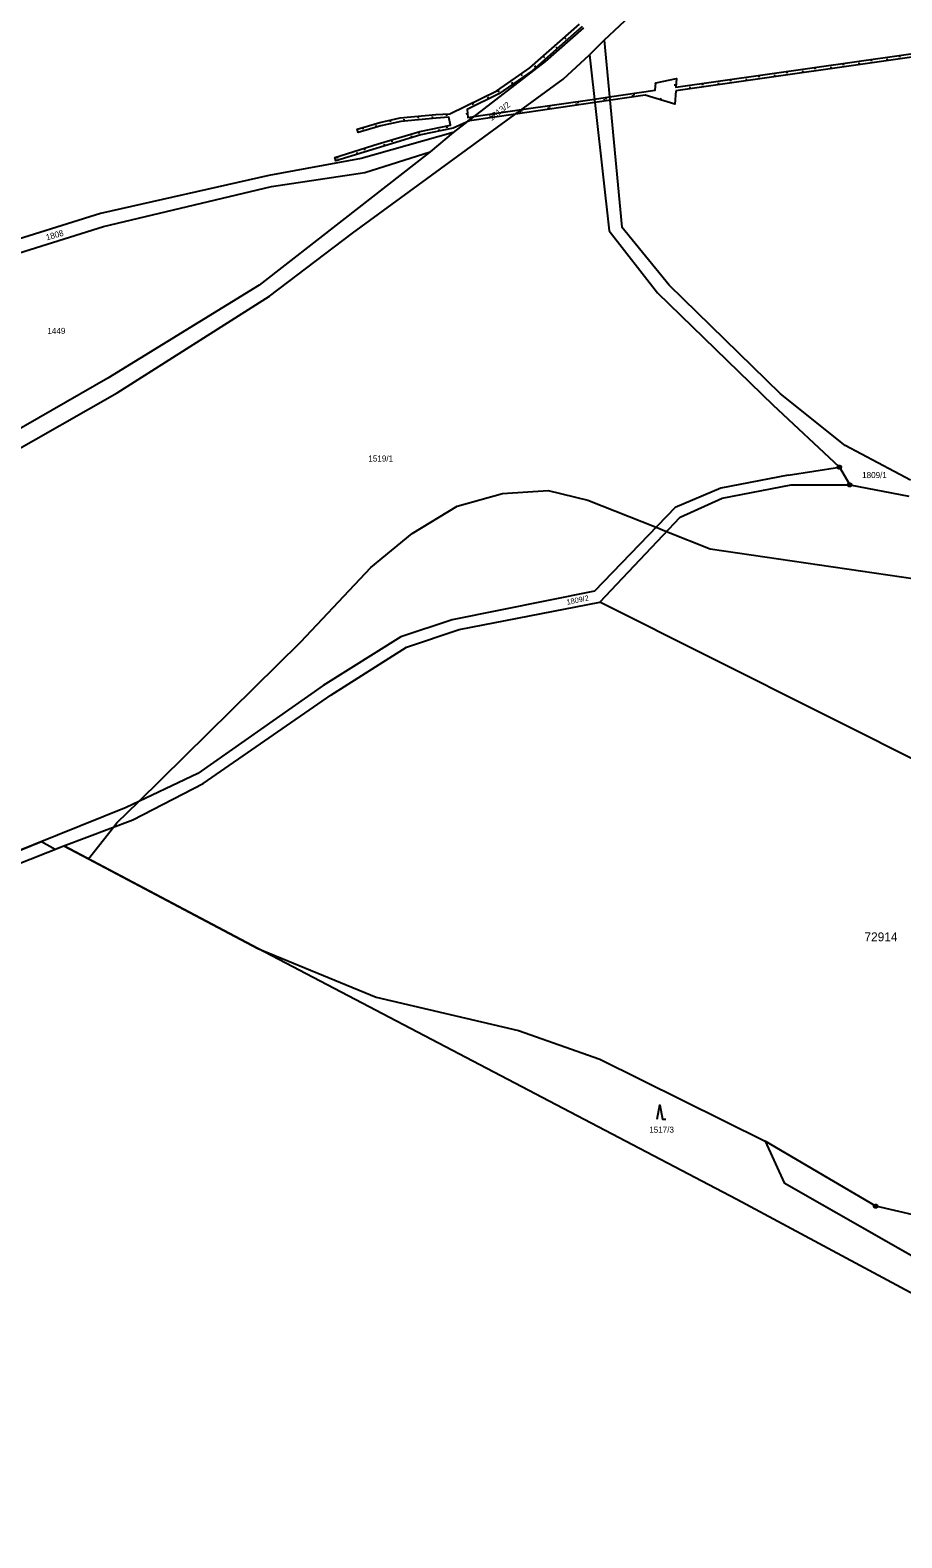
# Model space of a CAD drawing. Extents: x -779618 to -776429, y -1144546 to -1143350.
# Drawn here: x -778171.4 to -777926.1, y -1144528.8 to -1144104.5 of the extents above; entities that cross this region are included whole.
import ezdxf

# ---------------------------------------------------------------- set-up
doc = ezdxf.new("R2010")
doc.units = 0
for name, color, linetype in [('1', 7, 'Continuous'), ('11', 7, 'Continuous'), ('13', 7, 'Continuous'), ('2', 7, 'Continuous'), ('3', 7, 'Continuous'), ('8', 7, 'Continuous')]:
    doc.layers.add(name, color=color, linetype=linetype)

msp = doc.modelspace()

# ---------------------------------------------------------------- linework, layer by layer
at = {"layer": '1'}
for p, q in [((-778009.9, -1144107.25), (-777953.32, -1144054.13)), ((-778015.68, -1144103.79), (-778026.44, -1144113.3)), ((-778021.41, -1144118.27), (-778014.02, -1144111.36)), ((-778009.9, -1144107.25), (-778014.02, -1144111.36)), ((-778014.02, -1144111.36), (-778008.45, -1144160.92)), ((-778009.9, -1144107.25), (-778004.93, -1144159.92)), ((-778026.44, -1144113.3), (-778052.38, -1144133.24)), ((-778080.71, -1144161.6), (-778021.41, -1144118.27)), ((-778052.38, -1144133.24), (-778078.22, -1144140.59)), ((-778052.38, -1144133.24), (-778058.85, -1144138.68)), ((-778078.22, -1144140.59), (-778104.2, -1144145.33)), ((-778058.85, -1144138.68), (-778083.63, -1144158.04)), ((-778077.22, -1144144.48), (-778058.85, -1144138.68)), ((-778104.2, -1144145.33), (-778151.55, -1144156.01)), ((-778103.48, -1144148.43), (-778077.22, -1144144.48)), ((-778150.71, -1144159.71), (-778103.48, -1144148.43)), ((-778151.55, -1144156.01), (-778190.64, -1144168.24)), ((-778083.63, -1144158.04), (-778106.96, -1144176.23)), ((-778189.22, -1144171.73), (-778150.71, -1144159.71)), ((-778104.06, -1144179.35), (-778080.71, -1144161.6)), ((-778008.45, -1144160.92), (-777994.9, -1144178.38)), ((-777991.59, -1144176.2), (-778004.93, -1144159.92)), ((-778106.96, -1144176.23), (-778149.53, -1144202.42)), ((-777994.9, -1144178.38), (-777962.34, -1144209.95)), ((-777960.28, -1144206.84), (-777991.59, -1144176.2)), ((-778146.92, -1144206.52), (-778104.06, -1144179.35)), ((-778149.53, -1144202.42), (-778180.92, -1144220.4)), ((-778178.49, -1144224.58), (-778146.92, -1144206.52)), ((-777942.07, -1144221.33), (-777960.28, -1144206.84)), ((-777943.69, -1144227.42), (-777962.34, -1144209.95)), ((-777923.7, -1144231.09), (-777942.07, -1144221.33)), ((-777958.1, -1144229.69), (-777977.04, -1144233.33)), ((-777958.1, -1144229.69), (-777943.69, -1144227.42)), ((-777943.69, -1144227.42), (-777940.8, -1144232.44)), ((-777977.04, -1144233.33), (-777989.94, -1144238.83)), ((-777976.72, -1144236.21), (-777957.22, -1144232.42)), ((-777957.22, -1144232.42), (-777940.8, -1144232.44)), ((-777940.8, -1144232.44), (-777924.16, -1144235.57)), ((-777988.47, -1144241.5), (-777976.72, -1144236.21)), ((-777989.94, -1144238.83), (-778012.56, -1144262.31)), ((-778011.12, -1144265.48), (-777988.47, -1144241.5)), ((-778012.56, -1144262.31), (-778052.65, -1144270.41)), ((-778050.68, -1144273.14), (-778011.12, -1144265.48)), ((-777855.44, -1144343.58), (-778011.12, -1144265.48)), ((-778052.65, -1144270.41), (-778067.11, -1144275.18)), ((-778067.11, -1144275.18), (-778088.92, -1144288.94)), ((-778065.51, -1144278.13), (-778050.68, -1144273.14)), ((-778086.81, -1144291.59), (-778065.51, -1144278.13)), ((-778088.92, -1144288.94), (-778124.23, -1144313.7)), ((-778122.7, -1144316.51), (-778086.81, -1144291.59)), ((-778124.23, -1144313.7), (-778144.36, -1144323.21)), ((-778142.45, -1144326.7), (-778122.7, -1144316.51)), ((-778144.36, -1144323.21), (-778176.74, -1144336.28)), ((-778161.95, -1144334), (-778142.45, -1144326.7)), ((-778175.9, -1144339.55), (-778161.95, -1144334)), ((-778107.37, -1144362.89), (-778161.95, -1144334)), ((-778107.37, -1144362.89), (-778074.01, -1144376.57)), ((-777972.59, -1144433.55), (-778107.37, -1144362.89)), ((-778074.01, -1144376.57), (-778033.95, -1144386.03)), ((-778033.95, -1144386.03), (-778011.09, -1144394.05)), ((-778011.09, -1144394.05), (-777964.59, -1144417.15)), ((-777933.46, -1144435.4), (-777964.59, -1144417.15)), ((-777964.59, -1144417.15), (-777959.22, -1144428.87)), ((-777959.22, -1144428.87), (-777915.96, -1144453.57)), ((-777919.9, -1144461.76), (-777972.59, -1144433.55)), ((-777886.2, -1144446.52), (-777933.46, -1144435.4))]:
    msp.add_line(p, q, dxfattribs=at)
at = {"layer": '11'}
for points in [[(-778266.53, -1144276.65), (-778264.12, -1144275.43), (-778253.31, -1144268.82), (-778251.68, -1144267.86), (-778239.17, -1144258.55), (-778224.64, -1144251.87), (-778178.49, -1144224.58), (-778178.43, -1144228.31), (-778176.74, -1144336.28), (-778168.18, -1144332.82), (-778164.36, -1144334.96), (-778161.95, -1144334), (-778154.97, -1144337.7)], [(-778154.97, -1144337.7), (-778147.92, -1144328.75), (-778146.98, -1144327.55), (-778140.93, -1144321.59), (-778095.22, -1144276.56), (-778075.52, -1144255.69), (-778063.86, -1144246.1), (-778051.21, -1144238.41), (-778038.46, -1144234.87), (-778025.59, -1144234), (-778014.51, -1144236.71), (-777995.28, -1144244.37), (-777992.3, -1144245.55), (-777980.08, -1144250.42), (-777857.01, -1144268.43)], [(-778154.97, -1144337.7), (-778107.37, -1144362.89), (-778074.01, -1144376.57), (-778033.95, -1144386.03), (-778011.09, -1144394.05), (-777964.59, -1144417.15), (-777959.22, -1144428.87), (-777915.96, -1144453.57), (-777919.28, -1144460.47), (-777919.9, -1144461.76), (-777837.94, -1144505.62), (-777837.53, -1144505.84), (-777840.59, -1144507.92), (-777852.72, -1144518.48), (-777862.28, -1144528.78)]]:
    msp.add_lwpolyline(points, dxfattribs=at)
at = {"layer": '13'}
for p, q in [((-778021.04, -1144106.49), (-778020.71, -1144106.87)), ((-778023.1, -1144109.61), (-778023.43, -1144109.24)), ((-778029.09, -1144114.92), (-778029.42, -1144114.54)), ((-778027.04, -1144111.78), (-778026.71, -1144112.16)), ((-777950.63, -1144114.94), (-777950.56, -1144115.43)), ((-777945.98, -1144115.28), (-777946.05, -1144114.79)), ((-777942.71, -1144113.81), (-777942.64, -1144114.31)), ((-777938.06, -1144114.15), (-777938.13, -1144113.66)), ((-777934.79, -1144112.68), (-777934.72, -1144113.18)), ((-777930.14, -1144113.02), (-777930.21, -1144112.53)), ((-777926.87, -1144111.56), (-777926.8, -1144112.05)), ((-778035.55, -1144119.62), (-778035.84, -1144119.21)), ((-778033.25, -1144116.8), (-778032.96, -1144117.22)), ((-777995.55, -1144119.3), (-777995.45, -1144119.79)), ((-777982.31, -1144119.45), (-777982.24, -1144119.94)), ((-777977.66, -1144119.79), (-777977.73, -1144119.3)), ((-777974.39, -1144118.32), (-777974.32, -1144118.82)), ((-777969.74, -1144118.67), (-777969.81, -1144118.17)), ((-777966.47, -1144117.19), (-777966.4, -1144117.69)), ((-777961.82, -1144117.54), (-777961.89, -1144117.04)), ((-777958.55, -1144116.07), (-777958.48, -1144116.56)), ((-777953.9, -1144116.41), (-777953.97, -1144115.91)), ((-778042.35, -1144123.8), (-778042.57, -1144123.35)), ((-778039.82, -1144121.37), (-778039.53, -1144121.78)), ((-778009.68, -1144124.42), (-778009.75, -1144123.92)), ((-778009.48, -1144123.38), (-778009.41, -1144123.87)), ((-778001.76, -1144123.27), (-778001.83, -1144122.77)), ((-778001.57, -1144122.23), (-778001.49, -1144122.72)), ((-777994, -1144124.1), (-777993.85, -1144123.62)), ((-777989.66, -1144119.95), (-777990.15, -1144119.92)), ((-777985.58, -1144120.92), (-777985.65, -1144120.43)), ((-778054.28, -1144128.02), (-778054.26, -1144128.52)), ((-778048.31, -1144128.03), (-778048.81, -1144128.07)), ((-778046.99, -1144124.91), (-778046.77, -1144125.36)), ((-778041.15, -1144128), (-778041.08, -1144128.49)), ((-778033.43, -1144127.88), (-778033.5, -1144127.39)), ((-778033.23, -1144126.85), (-778033.16, -1144127.34)), ((-778025.51, -1144126.73), (-778025.58, -1144126.23)), ((-778025.31, -1144125.69), (-778025.24, -1144126.19)), ((-778017.6, -1144125.57), (-778017.67, -1144125.08)), ((-778017.4, -1144124.54), (-778017.33, -1144125.03)), ((-778077.89, -1144131.87), (-778077.75, -1144132.35)), ((-778073.9, -1144131.74), (-778074.04, -1144131.26)), ((-778070.16, -1144129.81), (-778070.05, -1144130.3)), ((-778066.09, -1144130.05), (-778066.13, -1144129.55)), ((-778062.26, -1144128.68), (-778062.21, -1144129.18)), ((-778058.12, -1144129.28), (-778058.17, -1144128.79)), ((-778056.19, -1144132.86), (-778056.29, -1144132.37)), ((-778054.27, -1144131.44), (-778054.17, -1144131.93)), ((-778048.64, -1144130.37), (-778046.59, -1144128.79)), ((-778046.59, -1144128.79), (-778048.64, -1144130.37)), ((-778041.34, -1144129.04), (-778041.42, -1144128.54)), ((-778071.62, -1144137.04), (-778071.76, -1144136.56)), ((-778069.76, -1144135.38), (-778069.62, -1144135.86)), ((-778063.96, -1144134.71), (-778064.11, -1144134.23)), ((-778062.11, -1144133.06), (-778062.01, -1144133.55)), ((-778085.06, -1144140.07), (-778084.91, -1144140.55)), ((-778079.27, -1144139.37), (-778079.42, -1144138.89)), ((-778077.42, -1144137.71), (-778077.27, -1144138.19))]:
    msp.add_line(p, q, dxfattribs=at)
for points in [[(-778046.59, -1144128.79), (-778033.12, -1144126.83), (-778012.62, -1144123.84), (-778008.39, -1144123.22), (-777995.49, -1144121.34), (-777995.33, -1144119.26), (-777989.54, -1144118.09), (-777989.69, -1144120.5), (-777912.98, -1144109.58), (-777833.61, -1144098.15), (-777749.52, -1144086.03), (-777662.82, -1144073.66), (-777659.12, -1144079.91), (-777658.45, -1144096.57), (-777659.45, -1144096.61), (-777660.1, -1144080.21), (-777663.34, -1144074.74), (-777749.38, -1144087.01), (-777833.47, -1144099.13), (-777912.84, -1144110.56), (-777989.71, -1144121.51)], [(-778048.64, -1144130.37), (-778052.35, -1144132.07), (-778061.5, -1144133.96), (-778085.36, -1144141.22), (-778085.66, -1144140.26), (-778073.44, -1144136.48), (-778061.74, -1144132.98), (-778053.11, -1144131.2), (-778053.59, -1144128.98), (-778057.16, -1144129.19), (-778067.13, -1144130.15), (-778072.75, -1144131.4), (-778079.11, -1144133.27), (-778079.39, -1144132.31), (-778072.99, -1144130.44), (-778067.29, -1144129.17), (-778057.24, -1144128.19), (-778053.31, -1144127.97), (-778040.07, -1144121.55), (-778030.77, -1144115.08), (-778016.81, -1144102.76)], [(-778016.07, -1144103.43), (-778022.45, -1144109.04), (-778030.15, -1144115.86), (-778039.55, -1144122.41), (-778048.41, -1144126.8), (-778048.23, -1144129.03), (-778046.59, -1144128.79)], [(-777989.71, -1144121.51), (-777990, -1144125.32), (-777998.36, -1144122.77), (-778012.51, -1144124.83), (-778034.85, -1144128.09), (-778047.79, -1144129.98), (-778048.64, -1144130.37)]]:
    msp.add_lwpolyline(points, dxfattribs=at)
at = {"layer": '3'}
msp.add_lwpolyline([(-777994.99, -1144410.95), (-777994.24, -1144406.95), (-777993.49, -1144410.95), (-777992.49, -1144410.95)], dxfattribs=at)
at = {"layer": '8'}
for p, q in [((-777943.81, -1144227.42), (-777943.57, -1144227.42)), ((-777940.92, -1144232.44), (-777940.68, -1144232.44)), ((-777933.58, -1144435.4), (-777933.34, -1144435.4))]:
    msp.add_line(p, q, dxfattribs=at)
for points in [[(-777943.54, -1144226.94), (-777943.29, -1144227.12), (-777943.19, -1144227.41), (-777943.29, -1144227.7), (-777943.54, -1144227.88), (-777943.85, -1144227.88), (-777944.1, -1144227.7), (-777944.2, -1144227.41), (-777944.1, -1144227.12), (-777943.85, -1144226.94)], [(-777940.65, -1144231.96), (-777940.4, -1144232.14), (-777940.3, -1144232.43), (-777940.4, -1144232.72), (-777940.65, -1144232.9), (-777940.96, -1144232.9), (-777941.21, -1144232.72), (-777941.31, -1144232.43), (-777941.21, -1144232.14), (-777940.96, -1144231.96)], [(-777933.31, -1144434.92), (-777933.06, -1144435.1), (-777932.96, -1144435.39), (-777933.06, -1144435.68), (-777933.31, -1144435.86), (-777933.62, -1144435.86), (-777933.87, -1144435.68), (-777933.97, -1144435.39), (-777933.87, -1144435.1), (-777933.62, -1144434.92)]]:
    msp.add_lwpolyline(points, close=True, dxfattribs=at)

# ---------------------------------------------------------------- texts
at = {"layer": '11'}
msp.add_text('72914', height=2.5, dxfattribs=at).set_placement((-777936.64, -1144360.88))
at = {"layer": '2'}
for s, height, rotation, p in [('1813/2', 1.7, 38.3309, (-778041.58, -1144130.09)), ('1808', 1.7, 15.699, (-778166.69, -1144163.63)), ('1809/2', 1.5, 11.5737, (-778020.29, -1144266.2))]:
    msp.add_text(s, height=height, rotation=rotation, dxfattribs=at).set_placement(p)
for s, p in [('1449', (-778166.53, -1144189.94)), ('1519/1', (-778076.22, -1144225.86)), ('1809/1', (-777937.3, -1144230.52)), ('1517/3', (-777997.2, -1144414.76))]:
    msp.add_text(s, height=1.7, dxfattribs=at).set_placement(p)

doc.saveas('drawing.dxf')
